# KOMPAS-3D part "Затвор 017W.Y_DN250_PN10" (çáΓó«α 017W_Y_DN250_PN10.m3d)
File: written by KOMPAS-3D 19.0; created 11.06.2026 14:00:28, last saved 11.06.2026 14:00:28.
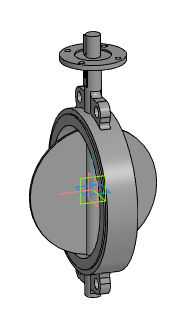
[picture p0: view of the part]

Document properties: Автор: Евгений; Полное имя файла: Z:\3.Личные\kachalov\001_3d для проектировщиков\x.x Тип 017W.Y(S) Затвор дисковый поворотный межфланцевый\_stp_Затвор 017W.Y_DN50-DN350\Затвор 017W_Y_DN250_PN10.m3d

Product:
- Part/product: Затвор 017W.Y_DN250_PN10

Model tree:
1. Операция без истории:1  (labels: Затвор 017W.Y_DN250_PN10)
